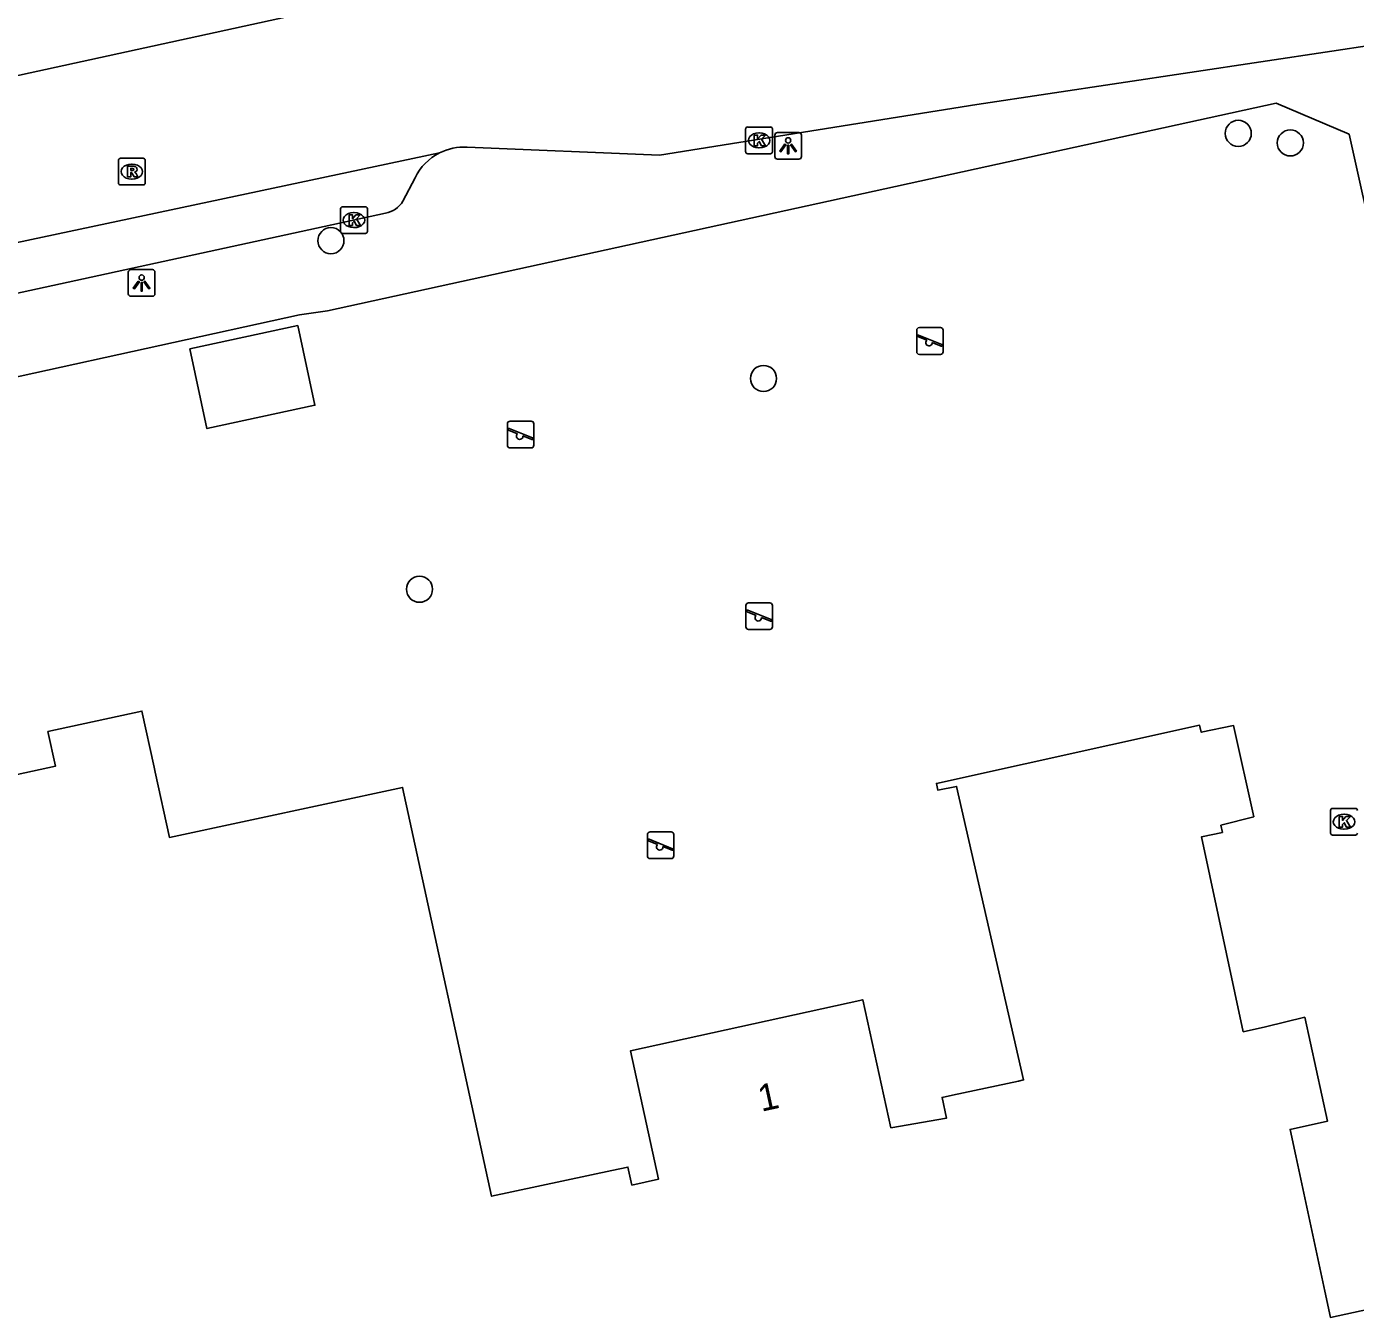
# Model space of a CAD drawing. Extents: x 160037 to 160839, y 385326 to 386441.
# Drawn here: x 160656.46 to 160706.19, y 385845.08 to 385893.36 of the extents above; entities that cross this region are included whole.
import ezdxf

# ---------------------------------------------------------------- set-up
doc = ezdxf.new("R2010")
doc.units = 0
for name, color, linetype in [('IMGEO_Boom', 7, 'Continuous'), ('IMGEO_Hek', 7, 'Continuous'), ('IMGEO_Kolk', 7, 'Continuous'), ('IMGEO_Lichtpunt', 7, 'Continuous'), ('IMGEO_Pand', 7, 'Continuous'), ('IMGEO_Pand_nummerreeks', 7, 'Continuous'), ('IMGEO_Rijbaan_lokaal_gesloten', 7, 'Continuous'), ('IMGEO_Rioolput', 7, 'Continuous'), ('IMGEO_Speelvoorziening', 7, 'Continuous'), ('IMGEO_Voetpad_open', 7, 'Continuous')]:
    doc.layers.add(name, color=color, linetype=linetype)

msp = doc.modelspace()

# ---------------------------------------------------------------- linework, layer by layer
at = {"layer": 'IMGEO_Boom'}
for centre in [(160701.803, 385889.369), (160703.751, 385889.013), (160667.85, 385885.356), (160684.038, 385880.201), (160671.166, 385872.316)]:
    msp.add_circle(centre, 0.489, dxfattribs=at)
at = {"layer": 'IMGEO_Hek'}
msp.add_lwpolyline([(160667.728, 385882.737), (160703.225, 385890.504), (160705.952, 385889.337)], dxfattribs=at)
at = {"layer": 'IMGEO_Kolk'}
for p, q in [((160683.37, 385888.682), (160683.37, 385889.534)), ((160683.445, 385889.608), (160684.297, 385889.608)), ((160684.371, 385889.534), (160684.371, 385888.682)), ((160683.858, 385889.388), (160683.883, 385889.388)), ((160684.297, 385888.608), (160683.445, 385888.608)), ((160683.881, 385888.828), (160683.856, 385888.828)), ((160668.212, 385885.699), (160668.212, 385886.551)), ((160668.287, 385886.625), (160669.139, 385886.625)), ((160669.213, 385886.551), (160669.213, 385885.699)), ((160668.7, 385886.405), (160668.725, 385886.405)), ((160669.139, 385885.625), (160668.287, 385885.625)), ((160668.723, 385885.845), (160668.698, 385885.845)), ((160705.335, 385864.118), (160706.187, 385864.118)), ((160705.26, 385863.192), (160705.26, 385864.044)), ((160705.748, 385863.898), (160705.773, 385863.898)), ((160706.187, 385863.118), (160705.335, 385863.118)), ((160705.771, 385863.338), (160705.746, 385863.338))]:
    msp.add_line(p, q, dxfattribs=at)
for points in [[(160683.37, 385888.682), (160683.37, 385889.534)], [(160683.445, 385889.608), (160684.297, 385889.608)], [(160684.371, 385889.534), (160684.371, 385888.682)], [(160683.691, 385889.308), (160683.814, 385889.308), (160683.814, 385889.157), (160683.944, 385889.308), (160684.108, 385889.308), (160683.962, 385889.157), (160684.115, 385888.908), (160683.963, 385888.908), (160683.878, 385889.072), (160683.814, 385889.005), (160683.814, 385888.908), (160683.691, 385888.908), (160683.691, 385889.308)], [(160684.297, 385888.608), (160683.445, 385888.608)], [(160668.212, 385885.699), (160668.212, 385886.551)], [(160668.287, 385886.625), (160669.139, 385886.625)], [(160669.213, 385886.551), (160669.213, 385885.699)], [(160668.533, 385886.325), (160668.656, 385886.325), (160668.656, 385886.174), (160668.786, 385886.325), (160668.95, 385886.325), (160668.804, 385886.174), (160668.957, 385885.925), (160668.805, 385885.925), (160668.72, 385886.089), (160668.656, 385886.022), (160668.656, 385885.925), (160668.533, 385885.925), (160668.533, 385886.325)], [(160669.139, 385885.625), (160668.287, 385885.625)], [(160705.335, 385864.118), (160706.187, 385864.118)], [(160705.26, 385863.192), (160705.26, 385864.044)], [(160705.581, 385863.818), (160705.704, 385863.818), (160705.704, 385863.667), (160705.834, 385863.818), (160705.998, 385863.818), (160705.852, 385863.667), (160706.005, 385863.418), (160705.853, 385863.418), (160705.768, 385863.582), (160705.704, 385863.515), (160705.704, 385863.418), (160705.581, 385863.418), (160705.581, 385863.818)], [(160706.187, 385863.118), (160705.335, 385863.118)]]:
    msp.add_lwpolyline(points, dxfattribs=at)
for centre, start, end in [((160683.447, 385889.532), 91.552, 178.448), ((160683.447, 385889.532), 91.552, 178.448), ((160684.295, 385889.532), 1.552, 88.448), ((160684.295, 385889.532), 1.552, 88.448), ((160683.447, 385888.684), 181.552, 268.448), ((160683.447, 385888.684), 181.552, 268.448), ((160684.295, 385888.684), 271.552, 358.448), ((160684.295, 385888.684), 271.552, 358.448), ((160668.289, 385886.549), 91.552, 178.448), ((160668.289, 385886.549), 91.552, 178.448), ((160669.137, 385886.549), 1.552, 88.448), ((160669.137, 385886.549), 1.552, 88.448), ((160668.289, 385885.701), 181.552, 268.448), ((160668.289, 385885.701), 181.552, 268.448), ((160669.137, 385885.701), 271.552, 358.448), ((160669.137, 385885.701), 271.552, 358.448), ((160705.337, 385864.042), 91.552, 178.448), ((160705.337, 385864.042), 91.552, 178.448), ((160706.185, 385864.042), 1.552, 88.448), ((160706.185, 385864.042), 1.552, 88.448), ((160705.337, 385863.194), 181.552, 268.448), ((160705.337, 385863.194), 181.552, 268.448), ((160706.185, 385863.194), 271.552, 358.448), ((160706.185, 385863.194), 271.552, 358.448)]:
    msp.add_arc(centre, 0.0765, start, end, dxfattribs=at)
for centre, major_axis, ratio, start_param, end_param in [((160683.857, 385889.108), (-0.387, 0.002), 0.722429, 4.712389, 7.853982), ((160683.882, 385889.108), (-0.39, 0.002), 0.717154, 1.570796, 4.712389), ((160668.699, 385886.125), (-0.387, 0.002), 0.722429, 4.712389, 7.853982), ((160668.724, 385886.125), (-0.39, 0.002), 0.717154, 1.570796, 4.712389), ((160705.747, 385863.618), (-0.387, 0.002), 0.722429, 4.712389, 7.853982), ((160705.772, 385863.618), (-0.39, 0.002), 0.717154, 1.570796, 4.712389)]:
    msp.add_ellipse(centre, major_axis=major_axis, ratio=ratio, start_param=start_param, end_param=end_param, dxfattribs=at)
at = {"layer": 'IMGEO_Lichtpunt'}
for p, q in [((160684.461, 385889.309), (160684.461, 385888.502)), ((160684.461, 385889.309), (160684.461, 385888.502)), ((160685.363, 385889.404), (160684.555, 385889.404)), ((160685.363, 385889.404), (160684.555, 385889.404)), ((160685.457, 385888.502), (160685.457, 385889.309)), ((160685.457, 385888.502), (160685.457, 385889.309)), ((160684.555, 385888.408), (160685.363, 385888.408)), ((160684.555, 385888.408), (160685.363, 385888.408)), ((160660.269, 385884.178), (160660.269, 385883.371)), ((160660.269, 385884.178), (160660.269, 385883.371)), ((160661.171, 385884.273), (160660.363, 385884.273)), ((160661.171, 385884.273), (160660.363, 385884.273)), ((160661.265, 385883.371), (160661.265, 385884.178)), ((160661.265, 385883.371), (160661.265, 385884.178)), ((160660.363, 385883.277), (160661.171, 385883.277)), ((160660.363, 385883.277), (160661.171, 385883.277))]:
    msp.add_line(p, q, dxfattribs=at)
for points in [[(160684.835, 385888.973), (160684.874, 385888.945), (160684.686, 385888.683), (160684.648, 385888.71), (160684.835, 385888.973)], [(160685.047, 385888.945), (160685.085, 385888.972), (160685.272, 385888.71), (160685.233, 385888.682), (160685.047, 385888.945)], [(160684.937, 385888.925), (160684.984, 385888.925), (160684.984, 385888.603), (160684.937, 385888.603), (160684.937, 385888.925)], [(160660.643, 385883.842), (160660.682, 385883.814), (160660.494, 385883.552), (160660.456, 385883.579), (160660.643, 385883.842)], [(160660.745, 385883.794), (160660.792, 385883.794), (160660.792, 385883.472), (160660.745, 385883.472), (160660.745, 385883.794)], [(160660.855, 385883.814), (160660.893, 385883.841), (160661.08, 385883.579), (160661.041, 385883.551), (160660.855, 385883.814)]]:
    msp.add_lwpolyline(points, dxfattribs=at)
for centre in [(160684.96, 385889.107), (160660.768, 385883.976)]:
    msp.add_circle(centre, 0.0994, dxfattribs=at)
for centre, start, end in [((160684.555, 385889.309), 90, 180), ((160684.555, 385889.309), 90, 180), ((160685.363, 385889.309), 0, 90), ((160685.363, 385889.309), 0, 90), ((160684.555, 385888.502), 180, 270), ((160684.555, 385888.502), 180, 270), ((160685.363, 385888.502), 270, 0), ((160685.363, 385888.502), 270, 360), ((160660.363, 385884.178), 90, 180), ((160660.363, 385884.178), 90, 180), ((160661.171, 385884.178), 0, 90), ((160661.171, 385884.178), 0, 90), ((160660.363, 385883.371), 180, 270), ((160660.363, 385883.371), 180, 270), ((160661.171, 385883.371), 270, 0), ((160661.171, 385883.371), 270, 360)]:
    msp.add_arc(centre, 0.0946, start, end, dxfattribs=at)
at = {"layer": 'IMGEO_Pand'}
for points in [[(160662.571, 385881.312), (160663.213, 385878.329), (160667.253, 385879.198), (160666.611, 385882.182), (160662.571, 385881.312)], [(160654.083, 385864.947), (160657.543, 385865.693), (160657.261, 385866.992), (160660.779, 385867.756), (160661.233, 385865.665), (160661.274, 385865.479), (160661.805, 385863.033), (160670.532, 385864.905), (160673.862, 385849.606), (160678.367, 385850.573), (160678.965, 385850.701), (160679.112, 385850.029), (160680.112, 385850.252), (160679.065, 385855.052), (160687.754, 385856.958), (160688.804, 385852.172), (160690.888, 385852.535), (160690.719, 385853.304), (160691.11, 385853.388), (160693.582, 385853.919), (160693.768, 385853.959), (160691.262, 385864.941), (160690.555, 385864.802), (160690.505, 385865.054), (160700.358, 385867.228), (160700.417, 385866.964), (160701.625, 385867.215), (160702.38, 385863.805), (160701.152, 385863.486), (160701.209, 385863.221), (160700.426, 385863.053), (160701.989, 385855.763), (160702.822, 385855.942), (160704.29, 385856.303), (160705.139, 385852.412), (160703.742, 385852.107), (160703.954, 385851.117), (160705.041, 385846.052), (160705.25, 385845.076), (160709.909, 385846.078)]]:
    msp.add_lwpolyline(points, dxfattribs=at)
at = {"layer": 'IMGEO_Rijbaan_lokaal_gesloten'}
for points in [[(160668.89, 385894.313), (160650.516, 385890.311)], [(160672.948, 385888.857), (160680.148, 385888.559), (160692.021, 385890.444), (160705.3, 385892.445), (160708.275, 385892.894)], [(160646.012, 385883.143), (160671.91, 385888.637)]]:
    msp.add_lwpolyline(points, dxfattribs=at)
msp.add_arc((160672.835, 385886.832), 2.028, 86.8041, 117.129, dxfattribs=at)
at = {"layer": 'IMGEO_Rioolput'}
for p, q in [((160659.9, 385887.514), (160659.9, 385888.366)), ((160659.975, 385888.44), (160660.827, 385888.44)), ((160660.388, 385888.22), (160660.413, 385888.22)), ((160660.901, 385888.366), (160660.901, 385887.514)), ((160660.411, 385887.66), (160660.386, 385887.66)), ((160660.827, 385887.44), (160659.975, 385887.44))]:
    msp.add_line(p, q, dxfattribs=at)
for points in [[(160659.9, 385887.514), (160659.9, 385888.366)], [(160659.975, 385888.44), (160660.827, 385888.44)], [(160660.489, 385888.138), (160660.237, 385888.14), (160660.237, 385887.74)], [(160660.415, 385888.059), (160660.361, 385888.059), (160660.361, 385887.978)], [(160660.361, 385887.978), (160660.413, 385887.978)], [(160660.901, 385888.366), (160660.901, 385887.514)], [(160660.237, 385887.74), (160660.361, 385887.74), (160660.361, 385887.902), (160660.372, 385887.902)], [(160660.419, 385887.873), (160660.49, 385887.74), (160660.63, 385887.74), (160660.565, 385887.866)], [(160660.827, 385887.44), (160659.975, 385887.44)]]:
    msp.add_lwpolyline(points, dxfattribs=at)
for centre, radius, start, end in [((160659.977, 385888.364), 0.0765, 91.552, 178.448), ((160659.977, 385888.364), 0.0765, 91.552, 178.448), ((160660.397, 385888.167), 0.19, 274.7715, 282.9687), ((160660.421, 385887.963), 0.0964, 77.0061, 93.1865), ((160660.435, 385888.02), 0.0378, 276.6634, 79.6772), ((160660.488, 385888.028), 0.109, 350.3612, 89.416), ((160660.486, 385888.028), 0.112, 277.5842, 350.9817), ((160660.825, 385888.364), 0.0765, 1.552, 88.448), ((160660.825, 385888.364), 0.0765, 1.552, 88.448), ((160659.977, 385887.516), 0.0765, 181.552, 268.448), ((160659.977, 385887.516), 0.0765, 181.552, 268.448), ((160660.371, 385887.849), 0.0533, 26.0293, 88.6989), ((160660.47, 385887.813), 0.108, 29.5134, 73.7905), ((160660.825, 385887.516), 0.0765, 271.552, 358.448), ((160660.825, 385887.516), 0.0765, 271.552, 358.448)]:
    msp.add_arc(centre, radius, start, end, dxfattribs=at)
for centre, major_axis, ratio, start_param, end_param in [((160660.387, 385887.94), (-0.387, 0.002), 0.722429, 4.712389, 7.853982), ((160660.412, 385887.94), (-0.39, 0.002), 0.717154, 1.570796, 4.712389)]:
    msp.add_ellipse(centre, major_axis=major_axis, ratio=ratio, start_param=start_param, end_param=end_param, dxfattribs=at)
at = {"layer": 'IMGEO_Speelvoorziening'}
for p, q in [((160689.87, 385882.102), (160690.66, 385882.102)), ((160690.66, 385882.102), (160689.87, 385882.102)), ((160689.77, 385881.202), (160689.77, 385882.002)), ((160689.77, 385882.002), (160689.77, 385881.202)), ((160690.153, 385881.63), (160689.814, 385881.767)), ((160689.839, 385881.827), (160690.715, 385881.474)), ((160690.691, 385881.414), (160690.351, 385881.551)), ((160690.76, 385882.002), (160690.76, 385881.202)), ((160690.76, 385881.202), (160690.76, 385882.002)), ((160690.66, 385881.102), (160689.87, 385881.102)), ((160689.87, 385881.102), (160690.66, 385881.102)), ((160674.553, 385878.603), (160675.343, 385878.603)), ((160675.343, 385878.603), (160674.553, 385878.603)), ((160674.453, 385877.703), (160674.453, 385878.503)), ((160674.453, 385878.503), (160674.453, 385877.703)), ((160674.836, 385878.131), (160674.497, 385878.268)), ((160674.522, 385878.328), (160675.398, 385877.975)), ((160675.374, 385877.915), (160675.034, 385878.052)), ((160675.443, 385878.503), (160675.443, 385877.703)), ((160675.443, 385877.703), (160675.443, 385878.503)), ((160675.343, 385877.603), (160674.553, 385877.603)), ((160674.553, 385877.603), (160675.343, 385877.603)), ((160683.381, 385870.909), (160683.381, 385871.709)), ((160683.381, 385871.709), (160683.381, 385870.909)), ((160683.481, 385871.809), (160684.271, 385871.809)), ((160684.271, 385871.809), (160683.481, 385871.809)), ((160684.371, 385871.709), (160684.371, 385870.909)), ((160684.371, 385870.909), (160684.371, 385871.709)), ((160683.764, 385871.337), (160683.425, 385871.474)), ((160683.45, 385871.534), (160684.326, 385871.181)), ((160684.302, 385871.121), (160683.962, 385871.258)), ((160684.271, 385870.809), (160683.481, 385870.809)), ((160683.481, 385870.809), (160684.271, 385870.809)), ((160679.693, 385862.339), (160679.693, 385863.139)), ((160679.693, 385863.139), (160679.693, 385862.339)), ((160679.793, 385863.239), (160680.583, 385863.239)), ((160680.583, 385863.239), (160679.793, 385863.239)), ((160680.683, 385863.139), (160680.683, 385862.339)), ((160680.683, 385862.339), (160680.683, 385863.139)), ((160680.076, 385862.767), (160679.737, 385862.904)), ((160679.762, 385862.964), (160680.638, 385862.611)), ((160680.614, 385862.551), (160680.274, 385862.688)), ((160680.583, 385862.239), (160679.793, 385862.239)), ((160679.793, 385862.239), (160680.583, 385862.239))]:
    msp.add_line(p, q, dxfattribs=at)
for centre, radius, start, end in [((160689.87, 385882.002), 0.1, 90, 180), ((160689.87, 385882.002), 0.1, 90, 180), ((160690.66, 385882.002), 0.1, 0, 90), ((160690.66, 385882.002), 0.1, 360, 90), ((160689.827, 385881.797), 0.0327, 68.078, 248.078), ((160690.232, 385881.54), 0.12, 130.9928, 5.1632), ((160689.87, 385881.202), 0.1, 180, 270), ((160689.87, 385881.202), 0.1, 180, 270), ((160690.66, 385881.202), 0.1, 270, 0), ((160690.66, 385881.202), 0.1, 270, 0), ((160690.703, 385881.444), 0.0327, 248.078, 68.078), ((160674.553, 385878.503), 0.1, 90, 180), ((160674.553, 385878.503), 0.1, 90, 180), ((160675.343, 385878.503), 0.1, 0, 90), ((160675.343, 385878.503), 0.1, 360, 90), ((160674.51, 385878.298), 0.0327, 68.078, 248.078), ((160674.915, 385878.041), 0.12, 130.9928, 5.1632), ((160674.553, 385877.703), 0.1, 180, 270), ((160674.553, 385877.703), 0.1, 180, 270), ((160675.343, 385877.703), 0.1, 270, 0), ((160675.343, 385877.703), 0.1, 270, 0), ((160675.386, 385877.945), 0.0327, 248.078, 68.078), ((160683.481, 385871.709), 0.1, 90, 180), ((160683.481, 385871.709), 0.1, 90, 180), ((160684.271, 385871.709), 0.1, 0, 90), ((160684.271, 385871.709), 0.1, 360, 90), ((160683.438, 385871.504), 0.0327, 68.078, 248.078), ((160683.843, 385871.247), 0.12, 130.9928, 5.1632), ((160684.314, 385871.151), 0.0327, 248.078, 68.078), ((160683.481, 385870.909), 0.1, 180, 270), ((160683.481, 385870.909), 0.1, 180, 270), ((160684.271, 385870.909), 0.1, 270, 0), ((160684.271, 385870.909), 0.1, 270, 0), ((160679.793, 385863.139), 0.1, 90, 180), ((160679.793, 385863.139), 0.1, 90, 180), ((160680.583, 385863.139), 0.1, 0, 90), ((160680.583, 385863.139), 0.1, 360, 90), ((160679.75, 385862.934), 0.0327, 68.078, 248.078), ((160680.155, 385862.677), 0.12, 130.9928, 5.1632), ((160679.793, 385862.339), 0.1, 180, 270), ((160679.793, 385862.339), 0.1, 180, 270), ((160680.583, 385862.339), 0.1, 270, 0), ((160680.583, 385862.339), 0.1, 270, 0), ((160680.626, 385862.581), 0.0327, 248.078, 68.078)]:
    msp.add_arc(centre, radius, start, end, dxfattribs=at)
at = {"layer": 'IMGEO_Voetpad_open'}
for points in [[(160715.104, 385846.987), (160707.016, 385884.582), (160705.952, 385889.337), (160703.225, 385890.504), (160667.728, 385882.737), (160666.678, 385882.585), (160650.98, 385879.145)], [(160670.998, 385887.708), (160670.547, 385886.828)], [(160669.892, 385886.381), (160649.397, 385881.93)]]:
    msp.add_lwpolyline(points, dxfattribs=at)
for centre, radius, start, end in [((160672.837, 385886.815), 2.044, 116.9578, 154.1004), ((160669.672, 385887.407), 1.049, 282.1092, 326.5134)]:
    msp.add_arc(centre, radius, start, end, dxfattribs=at)

# ---------------------------------------------------------------- texts
at = {"layer": 'IMGEO_Pand_nummerreeks'}
msp.add_text('1', height=1, rotation=12.3723, dxfattribs=at).set_placement((160683.955, 385852.766))

doc.saveas('drawing.dxf')
